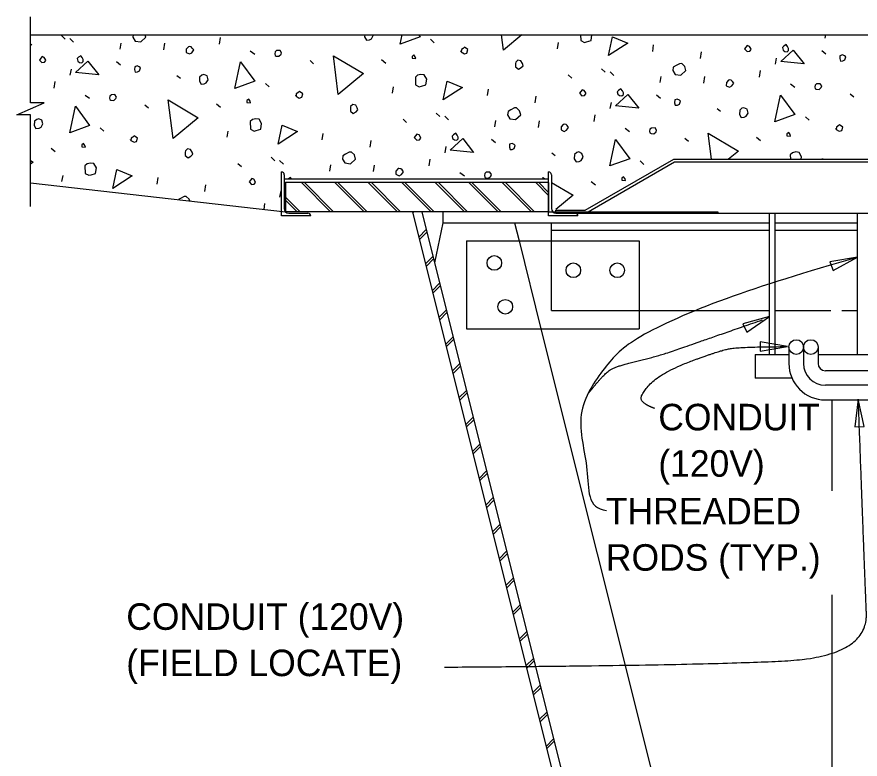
# Model space of a CAD drawing. Extents: x 927736.2 to 927809.6, y 636703.6 to 636757.7.
# Drawn here: x 927752.87 to 927764.73, y 636721.33 to 636731.77 of the extents above; entities that cross this region are included whole.
import ezdxf

# ---------------------------------------------------------------- set-up
doc = ezdxf.new("R2010")
doc.units = 0
for name, color, linetype in [('Default', 7, 'Continuous'), ('DimLines_dp', 7, 'Continuous'), ('Miscellaneous1', 7, 'Continuous'), ('Miscellaneous2', 7, 'Continuous'), ('Miscellaneous3', 7, 'Continuous')]:
    doc.layers.add(name, color=color, linetype=linetype)

msp = doc.modelspace()

# ---------------------------------------------------------------- linework, layer by layer
at = {"layer": 'Default'}
msp.add_line((927758.438, 636729.014), (927758.453, 636729.029), dxfattribs=at)
at = {"layer": 'DimLines_dp'}
msp.add_lwpolyline([(927753.063, 636729.104), (927753.063, 636730.392), (927752.871, 636730.392), (927753.063, 636730.476), (927753.254, 636730.559), (927753.063, 636730.559), (927753.063, 636731.768)], dxfattribs=at)
for points in [[(927764.692, 636728.389), (927764.306, 636728.326), (927764.349, 636728.202)], [(927763.458, 636727.557), (927763.081, 636727.455), (927763.135, 636727.336)], [(927763.711, 636727.133), (927763.325, 636727.199), (927763.325, 636727.068)], [(927764.705, 636726.393), (927764.654, 636726.006), (927764.785, 636726.011)]]:
    msp.add_lwpolyline(points, close=True, dxfattribs=at)
for points, degree in [([(927764.692, 636728.389), (927763.962, 636728.176), (927762.754, 636727.81), (927761.495, 636727.244), (927761.155, 636726.878), (927760.689, 636726.198), (927760.946, 636725.403), (927760.886, 636724.856), (927761.163, 636724.831)], 3), ([(927760.903, 636726.468), (927761.067, 636726.677), (927761.256, 636726.853), (927761.873, 636726.992), (927762.515, 636727.218), (927763.355, 636727.509)], 2), ([(927761.841, 636726.264), (927761.696, 636726.315), (927761.621, 636726.441), (927761.929, 636726.768), (927762.729, 636727.07), (927763.037, 636727.133), (927763.711, 636727.133)], 2), ([(927758.883, 636722.628), (927762.516, 636722.653), (927764.844, 636722.779), (927764.793, 636724), (927764.705, 636726.393)], 2)]:
    msp.add_open_spline(points, degree=degree, dxfattribs=at)
at = {"layer": 'Miscellaneous1'}
for p, q in [((927763.728, 636727.127), (927763.728, 636726.898)), ((927763.934, 636727.127), (927763.934, 636726.898)), ((927764.139, 636727.127), (927764.139, 636726.898)), ((927763.253, 636727.024), (927763.253, 636726.69)), ((927763.253, 636727.024), (927763.728, 636727.024)), ((927764.139, 636727.024), (927764.974, 636727.024)), ((927765.656, 636726.795), (927764.242, 636726.795)), ((927763.772, 636726.69), (927763.253, 636726.69)), ((927765.66, 636726.589), (927764.242, 636726.59)), ((927764.242, 636726.384), (927765.662, 636726.383))]:
    msp.add_line(p, q, dxfattribs=at)
for centre in [(927763.831, 636727.127), (927764.037, 636727.127)]:
    msp.add_circle(centre, 0.103, dxfattribs=at)
for radius in [0.514, 0.308, 0.103]:
    msp.add_arc((927764.242, 636726.898), radius, 180, 269.9792, dxfattribs=at)
at = {"layer": 'Miscellaneous2'}
for p, q in [((927753.063, 636731.515), (927774, 636731.515)), ((927753.498, 636731.507), (927753.55, 636731.457)), ((927753.618, 636731.463), (927753.67, 636731.413)), ((927755.72, 636731.387), (927755.733, 636731.48)), ((927758.689, 636731.455), (927758.741, 636731.405)), ((927764.24, 636731.468), (927764.248, 636731.515)), ((927753.063, 636731.391), (927753.08, 636731.376)), ((927754.322, 636731.313), (927754.337, 636731.4)), ((927754.937, 636731.305), (927754.951, 636731.398)), ((927760.475, 636731.321), (927760.49, 636731.408)), ((927761.813, 636731.283), (927761.826, 636731.376)), ((927756.154, 636731.293), (927756.217, 636731.246)), ((927762.485, 636731.183), (927762.498, 636731.275)), ((927763.54, 636731.102), (927763.555, 636731.189)), ((927764.191, 636731.295), (927764.249, 636731.247)), ((927754.273, 636731.14), (927754.331, 636731.092)), ((927756.995, 636731.155), (927757.045, 636731.11)), ((927758, 636731.168), (927758.058, 636731.12)), ((927753.623, 636730.947), (927753.638, 636731.034)), ((927755.123, 636730.946), (927755.171, 636730.908)), ((927760.625, 636730.952), (927760.675, 636730.908)), ((927761.093, 636731.039), (927761.144, 636730.989)), ((927761.213, 636730.995), (927761.265, 636730.945)), ((927763.315, 636730.92), (927763.328, 636731.013)), ((927753.397, 636730.765), (927753.41, 636730.858)), ((927756.366, 636730.833), (927756.418, 636730.783)), ((927761.917, 636730.845), (927761.932, 636730.932)), ((927762.532, 636730.838), (927762.546, 636730.931)), ((927763.749, 636730.825), (927763.812, 636730.779)), ((927758.152, 636730.698), (927758.167, 636730.785)), ((927759.49, 636730.661), (927759.503, 636730.754)), ((927753.831, 636730.67), (927753.894, 636730.624)), ((927760.161, 636730.56), (927760.175, 636730.653)), ((927761.868, 636730.673), (927761.925, 636730.624)), ((927764.59, 636730.687), (927764.64, 636730.643)), ((927754.672, 636730.532), (927754.722, 636730.488)), ((927755.677, 636730.546), (927755.735, 636730.498)), ((927761.217, 636730.479), (927761.232, 636730.566)), ((927762.718, 636730.479), (927762.766, 636730.441)), ((927758.77, 636730.417), (927758.821, 636730.367)), ((927758.89, 636730.373), (927758.942, 636730.323)), ((927760.992, 636730.297), (927761.005, 636730.39)), ((927763.961, 636730.365), (927764.013, 636730.315)), ((927758.302, 636730.33), (927758.352, 636730.286)), ((927759.594, 636730.223), (927759.609, 636730.31)), ((927760.209, 636730.215), (927760.223, 636730.308)), ((927754.043, 636730.21), (927754.095, 636730.16)), ((927755.829, 636730.076), (927755.844, 636730.163)), ((927757.167, 636730.038), (927757.18, 636730.131)), ((927761.425, 636730.203), (927761.489, 636730.156)), ((927757.838, 636729.938), (927757.852, 636730.031)), ((927759.545, 636730.05), (927759.602, 636730.002)), ((927762.267, 636730.064), (927762.317, 636730.02)), ((927763.272, 636730.078), (927763.33, 636730.03)), ((927753.354, 636729.923), (927753.412, 636729.875)), ((927758.894, 636729.857), (927758.909, 636729.944)), ((927756.447, 636729.795), (927756.498, 636729.745)), ((927758.669, 636729.675), (927758.682, 636729.768)), ((927760.395, 636729.856), (927760.443, 636729.818)), ((927760.864, 636729.049), (927762.11, 636729.768)), ((927762.11, 636729.768), (927774, 636729.768)), ((927755.978, 636729.707), (927756.029, 636729.663)), ((927756.567, 636729.75), (927756.619, 636729.7)), ((927757.271, 636729.6), (927757.286, 636729.687)), ((927757.886, 636729.593), (927757.899, 636729.686)), ((927760.874, 636729.01), (927762.121, 636729.73)), ((927761.638, 636729.743), (927761.69, 636729.693)), ((927762.121, 636729.73), (927774, 636729.73)), ((927753.506, 636729.453), (927753.521, 636729.54)), ((927756.593, 636728.972), (927756.593, 636729.588)), ((927756.631, 636729.55), (927756.631, 636729.074)), ((927759.102, 636729.58), (927759.166, 636729.534)), ((927760.35, 636728.972), (927760.35, 636729.588)), ((927760.389, 636729.55), (927760.389, 636729.074)), ((927753.063, 636729.436), (927756.65, 636729.029)), ((927754.844, 636729.416), (927754.857, 636729.509)), ((927755.515, 636729.315), (927755.529, 636729.408)), ((927756.631, 636729.491), (927760.35, 636729.491)), ((927756.631, 636729.44), (927756.65, 636729.44)), ((927757.283, 636729.029), (927756.872, 636729.44)), ((927757.326, 636729.029), (927756.915, 636729.44)), ((927757.754, 636729.029), (927757.343, 636729.44)), ((927757.797, 636729.029), (927757.386, 636729.44)), ((927758.225, 636729.029), (927757.813, 636729.44)), ((927758.268, 636729.029), (927757.857, 636729.44)), ((927758.696, 636729.029), (927758.284, 636729.44)), ((927758.739, 636729.029), (927758.328, 636729.44)), ((927759.167, 636729.029), (927758.755, 636729.44)), ((927759.21, 636729.029), (927758.799, 636729.44)), ((927759.638, 636729.029), (927759.226, 636729.44)), ((927759.681, 636729.029), (927759.27, 636729.44)), ((927760.108, 636729.029), (927759.697, 636729.44)), ((927760.152, 636729.029), (927759.741, 636729.44)), ((927760.35, 636729.258), (927760.168, 636729.44)), ((927760.35, 636729.302), (927760.212, 636729.44)), ((927760.35, 636729.44), (927760.35, 636729.029)), ((927760.949, 636729.456), (927761.007, 636729.408)), ((927756.571, 636729.234), (927756.586, 636729.321)), ((927756.856, 636729.029), (927756.65, 636729.234)), ((927756.812, 636729.029), (927756.65, 636729.191)), ((927756.347, 636729.063), (927756.359, 636729.145)), ((927760.453, 636729.049), (927760.864, 636729.049)), ((927760.453, 636729.01), (927760.453, 636729.049)), ((927757.004, 636728.971), (927756.593, 636728.972)), ((927756.695, 636729.01), (927756.965, 636729.01)), ((927760.344, 636729.029), (927760.35, 636729.035)), ((927760.344, 636729.029), (927760.35, 636729.035)), ((927760.761, 636728.972), (927760.35, 636728.972)), ((927760.453, 636729.01), (927760.723, 636729.01)), ((927760.453, 636729.01), (927774, 636729.01))]:
    msp.add_line(p, q, dxfattribs=at)
for points in [[(927754.501, 636731.482), (927754.534, 636731.427), (927754.614, 636731.417), (927754.686, 636731.481), (927754.677, 636731.515)], [(927754.505, 636731.515), (927754.501, 636731.482)], [(927757.763, 636731.515), (927757.761, 636731.488), (927757.786, 636731.443), (927757.829, 636731.448), (927757.858, 636731.462), (927757.884, 636731.508), (927757.882, 636731.515)], [(927758.261, 636731.385), (927758.289, 636731.515)], [(927758.519, 636731.515), (927758.541, 636731.486), (927758.261, 636731.385)], [(927759.714, 636731.302), (927759.687, 636731.515)], [(927759.972, 636731.515), (927759.714, 636731.302)], [(927760.799, 636731.515), (927760.802, 636731.434), (927760.853, 636731.409), (927760.883, 636731.417), (927760.949, 636731.435), (927760.959, 636731.514), (927760.959, 636731.515)], [(927761.19, 636731.225), (927761.247, 636731.489), (927761.462, 636731.4), (927761.19, 636731.225)], [(927755.254, 636731.314), (927755.254, 636731.269), (927755.297, 636731.249), (927755.331, 636731.264), (927755.359, 636731.303), (927755.339, 636731.33), (927755.323, 636731.345), (927755.296, 636731.35), (927755.284, 636731.347), (927755.254, 636731.314)], [(927756.503, 636731.227), (927756.518, 636731.218), (927756.557, 636731.216), (927756.588, 636731.243), (927756.595, 636731.264), (927756.574, 636731.297), (927756.523, 636731.296), (927756.503, 636731.278), (927756.497, 636731.251), (927756.503, 636731.227)], [(927759.12, 636731.277), (927759.166, 636731.251), (927759.201, 636731.26), (927759.214, 636731.309), (927759.167, 636731.341), (927759.146, 636731.322), (927759.124, 636731.31), (927759.12, 636731.277), (927759.117, 636731.289)], [(927763.106, 636731.317), (927763.141, 636731.282), (927763.178, 636731.285), (927763.197, 636731.31), (927763.194, 636731.322), (927763.173, 636731.354), (927763.144, 636731.366), (927763.125, 636731.341), (927763.106, 636731.317)], [(927763.613, 636731.14), (927763.787, 636731.302), (927763.941, 636731.107), (927763.613, 636731.14)], [(927763.646, 636731.302), (927763.671, 636731.283), (927763.703, 636731.279), (927763.724, 636731.298), (927763.724, 636731.323), (927763.71, 636731.351), (927763.69, 636731.378), (927763.657, 636731.356), (927763.637, 636731.338), (927763.646, 636731.302)], [(927753.188, 636731.162), (927753.223, 636731.127), (927753.26, 636731.131), (927753.28, 636731.155), (927753.276, 636731.167), (927753.255, 636731.199), (927753.226, 636731.211), (927753.207, 636731.187), (927753.188, 636731.162)], [(927753.728, 636731.147), (927753.753, 636731.128), (927753.786, 636731.124), (927753.806, 636731.143), (927753.806, 636731.168), (927753.792, 636731.196), (927753.772, 636731.223), (927753.739, 636731.201), (927753.719, 636731.183), (927753.728, 636731.147)], [(927757.391, 636730.679), (927757.322, 636731.223), (927757.746, 636730.973), (927757.391, 636730.679)], [(927758.429, 636731.188), (927758.482, 636731.183), (927758.475, 636731.206), (927758.455, 636731.233), (927758.429, 636731.213), (927758.429, 636731.188)], [(927764.444, 636731.184), (927764.454, 636731.148), (927764.485, 636731.15), (927764.513, 636731.164), (927764.527, 636731.206), (927764.511, 636731.221), (927764.482, 636731.233), (927764.446, 636731.223), (927764.444, 636731.184)], [(927753.695, 636730.985), (927753.869, 636731.147), (927754.023, 636730.952), (927753.695, 636730.985)], [(927754.526, 636731.029), (927754.536, 636730.993), (927754.567, 636730.995), (927754.595, 636731.009), (927754.61, 636731.052), (927754.593, 636731.066), (927754.564, 636731.078), (927754.529, 636731.068), (927754.526, 636731.029)], [(927755.938, 636730.763), (927756.017, 636731.135), (927756.218, 636730.863), (927755.938, 636730.763)], [(927759.886, 636731.112), (927759.885, 636731.067), (927759.926, 636731.033), (927759.965, 636731.056), (927759.99, 636731.082), (927759.982, 636731.112), (927759.959, 636731.151), (927759.918, 636731.159), (927759.887, 636731.131), (927759.886, 636731.112)], [(927762.095, 636731.014), (927762.129, 636730.96), (927762.209, 636730.949), (927762.281, 636731.013), (927762.265, 636731.073), (927762.222, 636731.112), (927762.191, 636731.11), (927762.141, 636731.084), (927762.102, 636731.061), (927762.095, 636731.014)], [(927755.442, 636730.923), (927755.438, 636730.865), (927755.463, 636730.821), (927755.506, 636730.826), (927755.535, 636730.84), (927755.561, 636730.885), (927755.546, 636730.939), (927755.503, 636730.959), (927755.473, 636730.951), (927755.442, 636730.923)], [(927758.476, 636730.919), (927758.479, 636730.811), (927758.53, 636730.787), (927758.56, 636730.795), (927758.625, 636730.812), (927758.636, 636730.892), (927758.601, 636730.953), (927758.554, 636730.959), (927758.507, 636730.947), (927758.476, 636730.919)], [(927758.867, 636730.603), (927758.924, 636730.867), (927759.139, 636730.778), (927758.867, 636730.603)], [(927762.849, 636730.846), (927762.848, 636730.801), (927762.892, 636730.781), (927762.926, 636730.797), (927762.954, 636730.836), (927762.934, 636730.862), (927762.917, 636730.877), (927762.89, 636730.883), (927762.879, 636730.88), (927762.849, 636730.846)], [(927764.098, 636730.759), (927764.113, 636730.751), (927764.152, 636730.748), (927764.183, 636730.776), (927764.19, 636730.797), (927764.169, 636730.829), (927764.118, 636730.829), (927764.097, 636730.81), (927764.092, 636730.783), (927764.098, 636730.759)], [(927756.797, 636730.655), (927756.843, 636730.628), (927756.878, 636730.638), (927756.891, 636730.686), (927756.844, 636730.718), (927756.823, 636730.7), (927756.801, 636730.688), (927756.797, 636730.655), (927756.794, 636730.666)], [(927760.783, 636730.695), (927760.818, 636730.659), (927760.855, 636730.663), (927760.874, 636730.687), (927760.871, 636730.699), (927760.85, 636730.732), (927760.821, 636730.743), (927760.802, 636730.719), (927760.783, 636730.695)], [(927761.323, 636730.68), (927761.347, 636730.661), (927761.38, 636730.657), (927761.401, 636730.675), (927761.401, 636730.701), (927761.387, 636730.729), (927761.367, 636730.755), (927761.334, 636730.734), (927761.314, 636730.716), (927761.323, 636730.68)], [(927754.18, 636730.605), (927754.195, 636730.596), (927754.234, 636730.593), (927754.265, 636730.621), (927754.272, 636730.642), (927754.251, 636730.675), (927754.2, 636730.674), (927754.179, 636730.655), (927754.174, 636730.628), (927754.18, 636730.605)], [(927755.068, 636730.057), (927754.999, 636730.6), (927755.423, 636730.35), (927755.068, 636730.057)], [(927756.106, 636730.565), (927756.159, 636730.56), (927756.152, 636730.584), (927756.132, 636730.61), (927756.106, 636730.591), (927756.106, 636730.565)], [(927761.29, 636730.518), (927761.464, 636730.679), (927761.618, 636730.484), (927761.29, 636730.518)], [(927762.121, 636730.562), (927762.131, 636730.526), (927762.162, 636730.528), (927762.19, 636730.542), (927762.204, 636730.584), (927762.188, 636730.599), (927762.159, 636730.61), (927762.123, 636730.601), (927762.121, 636730.562)], [(927763.533, 636730.295), (927763.612, 636730.667), (927763.813, 636730.396), (927763.533, 636730.295)], [(927753.615, 636730.14), (927753.694, 636730.513), (927753.895, 636730.241), (927753.615, 636730.14)], [(927757.563, 636730.489), (927757.562, 636730.445), (927757.603, 636730.411), (927757.642, 636730.434), (927757.667, 636730.46), (927757.659, 636730.49), (927757.636, 636730.528), (927757.595, 636730.536), (927757.564, 636730.509), (927757.563, 636730.489)], [(927759.772, 636730.392), (927759.806, 636730.337), (927759.886, 636730.327), (927759.958, 636730.391), (927759.942, 636730.45), (927759.899, 636730.49), (927759.868, 636730.488), (927759.818, 636730.462), (927759.779, 636730.438), (927759.772, 636730.392)], [(927763.037, 636730.456), (927763.033, 636730.397), (927763.058, 636730.353), (927763.101, 636730.358), (927763.129, 636730.372), (927763.156, 636730.417), (927763.141, 636730.471), (927763.097, 636730.491), (927763.068, 636730.483), (927763.037, 636730.456)], [(927753.119, 636730.301), (927753.115, 636730.243), (927753.14, 636730.198), (927753.183, 636730.203), (927753.212, 636730.217), (927753.238, 636730.263), (927753.223, 636730.316), (927753.18, 636730.336), (927753.15, 636730.328), (927753.119, 636730.301)], [(927756.153, 636730.297), (927756.156, 636730.189), (927756.207, 636730.164), (927756.237, 636730.172), (927756.302, 636730.19), (927756.313, 636730.269), (927756.278, 636730.33), (927756.231, 636730.337), (927756.183, 636730.324), (927756.153, 636730.297)], [(927756.544, 636729.98), (927756.601, 636730.244), (927756.816, 636730.155), (927756.544, 636729.98)], [(927760.526, 636730.224), (927760.525, 636730.179), (927760.569, 636730.159), (927760.603, 636730.174), (927760.631, 636730.213), (927760.611, 636730.24), (927760.594, 636730.255), (927760.567, 636730.26), (927760.555, 636730.257), (927760.526, 636730.224)], [(927764.392, 636730.187), (927764.437, 636730.161), (927764.473, 636730.17), (927764.486, 636730.218), (927764.439, 636730.251), (927764.418, 636730.232), (927764.396, 636730.22), (927764.392, 636730.187), (927764.389, 636730.199)], [(927758.46, 636730.072), (927758.495, 636730.037), (927758.532, 636730.041), (927758.551, 636730.065), (927758.548, 636730.077), (927758.527, 636730.109), (927758.498, 636730.121), (927758.479, 636730.096), (927758.46, 636730.072)], [(927759, 636730.057), (927759.024, 636730.038), (927759.057, 636730.034), (927759.078, 636730.053), (927759.078, 636730.078), (927759.064, 636730.106), (927759.044, 636730.133), (927759.011, 636730.111), (927758.991, 636730.093), (927759, 636730.057)], [(927761.775, 636730.137), (927761.79, 636730.128), (927761.829, 636730.126), (927761.86, 636730.153), (927761.867, 636730.174), (927761.846, 636730.207), (927761.795, 636730.206), (927761.774, 636730.188), (927761.769, 636730.161), (927761.775, 636730.137)], [(927762.64, 636729.768), (927762.593, 636730.133), (927763.018, 636729.883), (927762.879, 636729.768)], [(927763.701, 636730.098), (927763.753, 636730.092), (927763.747, 636730.116), (927763.727, 636730.143), (927763.701, 636730.123), (927763.701, 636730.098)], [(927754.474, 636730.032), (927754.519, 636730.006), (927754.555, 636730.016), (927754.568, 636730.064), (927754.521, 636730.096), (927754.5, 636730.077), (927754.478, 636730.065), (927754.474, 636730.032), (927754.471, 636730.044)], [(927758.967, 636729.895), (927759.141, 636730.057), (927759.295, 636729.862), (927758.967, 636729.895)], [(927761.21, 636729.673), (927761.289, 636730.045), (927761.49, 636729.773), (927761.21, 636729.673)], [(927753.783, 636729.943), (927753.836, 636729.938), (927753.829, 636729.961), (927753.809, 636729.988), (927753.783, 636729.968), (927753.783, 636729.943)], [(927755.24, 636729.867), (927755.239, 636729.822), (927755.28, 636729.788), (927755.319, 636729.811), (927755.344, 636729.837), (927755.336, 636729.867), (927755.312, 636729.906), (927755.272, 636729.914), (927755.241, 636729.886), (927755.24, 636729.867)], [(927759.798, 636729.939), (927759.808, 636729.903), (927759.839, 636729.905), (927759.867, 636729.919), (927759.881, 636729.962), (927759.865, 636729.976), (927759.836, 636729.988), (927759.8, 636729.978), (927759.798, 636729.939)], [(927757.449, 636729.77), (927757.483, 636729.715), (927757.563, 636729.704), (927757.635, 636729.768), (927757.619, 636729.828), (927757.576, 636729.867), (927757.545, 636729.865), (927757.495, 636729.839), (927757.456, 636729.816), (927757.449, 636729.77)], [(927760.714, 636729.833), (927760.71, 636729.775), (927760.735, 636729.731), (927760.778, 636729.736), (927760.806, 636729.75), (927760.833, 636729.795), (927760.818, 636729.849), (927760.774, 636729.869), (927760.745, 636729.861), (927760.714, 636729.833)], [(927763.903, 636729.768), (927763.908, 636729.802), (927763.872, 636729.863), (927763.826, 636729.869), (927763.778, 636729.857), (927763.747, 636729.829)], [(927763.747, 636729.829), (927763.749, 636729.768)], [(927764.194, 636729.768), (927764.195, 636729.777), (927764.216, 636729.768)], [(927753.063, 636729.75), (927753.1, 636729.728), (927753.063, 636729.697)], [(927753.829, 636729.674), (927753.833, 636729.567), (927753.884, 636729.542), (927753.914, 636729.55), (927753.979, 636729.568), (927753.99, 636729.647), (927753.955, 636729.708), (927753.908, 636729.714), (927753.86, 636729.702), (927753.829, 636729.674)], [(927758.203, 636729.601), (927758.202, 636729.556), (927758.246, 636729.536), (927758.28, 636729.552), (927758.308, 636729.591), (927758.288, 636729.618), (927758.271, 636729.632), (927758.244, 636729.638), (927758.232, 636729.635), (927758.203, 636729.601)], [(927754.221, 636729.358), (927754.278, 636729.622), (927754.493, 636729.533), (927754.221, 636729.358)], [(927759.452, 636729.515), (927759.467, 636729.506), (927759.506, 636729.503), (927759.537, 636729.531), (927759.544, 636729.552), (927759.523, 636729.584), (927759.472, 636729.584), (927759.451, 636729.565), (927759.446, 636729.538), (927759.452, 636729.515)], [(927761.378, 636729.475), (927761.43, 636729.47), (927761.424, 636729.494), (927761.404, 636729.52), (927761.377, 636729.501), (927761.378, 636729.475)], [(927756.137, 636729.45), (927756.172, 636729.414), (927756.209, 636729.418), (927756.228, 636729.442), (927756.225, 636729.454), (927756.204, 636729.487), (927756.175, 636729.498), (927756.156, 636729.474), (927756.137, 636729.45)], [(927756.735, 636729.491), (927756.721, 636729.51), (927756.692, 636729.491)], [(927760.273, 636729.491), (927760.27, 636729.51), (927760.303, 636729.491)], [(927760.389, 636729.441), (927760.695, 636729.26), (927760.451, 636729.059)], [(927755.302, 636729.182), (927755.296, 636729.205), (927755.253, 636729.245), (927755.222, 636729.243), (927755.171, 636729.217), (927755.144, 636729.2)]]:
    msp.add_lwpolyline(points, dxfattribs=at)
for centre, radius, start, end in [((927756.593, 636729.55), 0.0385, 359.9953, 89.9953), ((927760.35, 636729.55), 0.0385, 359.9953, 89.9953), ((927756.695, 636729.074), 0.0642, 179.9953, 269.9953), ((927760.453, 636729.074), 0.0642, 179.9953, 269.9953), ((927756.965, 636728.971), 0.0385, 359.9953, 89.9953), ((927760.723, 636728.972), 0.0385, 359.9953, 89.9953)]:
    msp.add_arc(centre, radius, start, end, dxfattribs=at)
at = {"layer": 'Miscellaneous3'}
for p, q in [((927760.35, 636729.44), (927756.65, 636729.44)), ((927756.65, 636729.44), (927756.65, 636729.029)), ((927760.35, 636729.029), (927756.65, 636729.029)), ((927758.434, 636729.029), (927762.288, 636713.612)), ((927758.566, 636729.029), (927762.42, 636713.612)), ((927758.867, 636728.875), (927758.867, 636729.029)), ((927760.35, 636729.029), (927762.729, 636729.029)), ((927762.729, 636729.029), (927762.729, 636729.01)), ((927763.458, 636727.024), (927763.458, 636729.01)), ((927763.535, 636727.024), (927763.535, 636729.01)), ((927764.692, 636727.024), (927764.692, 636729.01)), ((927758.862, 636728.875), (927758.745, 636728.313)), ((927758.867, 636728.875), (927763.458, 636728.875)), ((927759.868, 636728.875), (927759.933, 636728.618)), ((927760.389, 636728.592), (927760.389, 636728.875)), ((927763.535, 636728.875), (927764.692, 636728.874)), ((927758.523, 636728.672), (927758.629, 636728.778)), ((927758.532, 636728.637), (927758.638, 636728.743)), ((927760.389, 636727.641), (927760.389, 636728.772)), ((927760.389, 636728.772), (927763.458, 636728.772)), ((927763.535, 636728.772), (927764.692, 636728.772)), ((927759.194, 636728.618), (927759.194, 636727.384)), ((927759.194, 636728.618), (927761.622, 636728.618)), ((927759.933, 636728.618), (927760.241, 636727.384)), ((927761.622, 636728.618), (927761.622, 636727.384)), ((927758.617, 636728.295), (927758.723, 636728.401)), ((927758.626, 636728.26), (927758.732, 636728.366)), ((927758.711, 636727.918), (927758.817, 636728.024)), ((927758.72, 636727.883), (927758.826, 636727.989)), ((927758.806, 636727.542), (927758.912, 636727.648)), ((927760.389, 636727.641), (927761.622, 636727.641)), ((927761.622, 636727.641), (927763.458, 636727.641)), ((927763.535, 636727.641), (927764.319, 636727.641)), ((927764.473, 636727.641), (927764.692, 636727.641)), ((927758.814, 636727.507), (927758.92, 636727.613)), ((927759.194, 636727.384), (927761.622, 636727.384)), ((927760.241, 636727.384), (927762.676, 636717.646)), ((927758.9, 636727.165), (927759.006, 636727.271)), ((927758.909, 636727.13), (927759.015, 636727.236)), ((927758.994, 636726.788), (927759.1, 636726.894)), ((927759.003, 636726.753), (927759.109, 636726.859)), ((927759.088, 636726.411), (927759.194, 636726.517)), ((927759.097, 636726.376), (927759.203, 636726.482)), ((927759.182, 636726.035), (927759.288, 636726.141)), ((927759.191, 636726), (927759.297, 636726.106)), ((927759.277, 636725.658), (927759.383, 636725.764)), ((927759.285, 636725.623), (927759.391, 636725.729)), ((927759.371, 636725.281), (927759.477, 636725.387)), ((927759.379, 636725.246), (927759.485, 636725.352)), ((927759.465, 636724.904), (927759.571, 636725.01)), ((927759.474, 636724.869), (927759.58, 636724.975)), ((927759.559, 636724.528), (927759.665, 636724.634)), ((927759.568, 636724.493), (927759.674, 636724.599)), ((927759.653, 636724.151), (927759.759, 636724.257)), ((927759.662, 636724.116), (927759.768, 636724.222)), ((927759.748, 636723.774), (927759.853, 636723.88)), ((927759.756, 636723.739), (927759.862, 636723.845)), ((927759.842, 636723.397), (927759.948, 636723.503)), ((927759.85, 636723.362), (927759.956, 636723.468)), ((927759.936, 636723.021), (927760.042, 636723.127)), ((927759.945, 636722.986), (927760.051, 636723.092)), ((927760.03, 636722.644), (927760.136, 636722.75)), ((927760.039, 636722.609), (927760.145, 636722.715)), ((927760.124, 636722.267), (927760.23, 636722.373)), ((927760.133, 636722.232), (927760.239, 636722.338)), ((927760.218, 636721.89), (927760.324, 636721.996)), ((927760.227, 636721.856), (927760.333, 636721.961)), ((927760.313, 636721.514), (927760.419, 636721.62)), ((927760.321, 636721.479), (927760.427, 636721.585))]:
    msp.add_line(p, q, dxfattribs=at)
for points in [[(927764.332, 636726.384), (927764.332, 636725.108)], [(927764.332, 636723.646), (927764.332, 636718.446), (927768.032, 636718.446)]]:
    msp.add_lwpolyline(points, dxfattribs=at)
for centre in [(927759.586, 636728.309), (927760.697, 636728.206), (927761.314, 636728.206), (927759.74, 636727.693)]:
    msp.add_circle(centre, 0.103, dxfattribs=at)

# ---------------------------------------------------------------- texts
at = {"layer": 'DimLines_dp'}
for s, height, p in [('CONDUIT', 0.373, (927761.892, 636725.956)), ('(120V)', 0.373, (927761.892, 636725.304)), ('THREADED', 0.373, (927761.155, 636724.634)), ('RODS (TYP.)', 0.37296, (927761.155, 636723.983)), ('CONDUIT (120V)', 0.37296, (927754.41, 636723.152)), ('(FIELD LOCATE)', 0.37296, (927754.41, 636722.501))]:
    msp.add_text(s, height=height, dxfattribs=at).set_placement(p)

doc.saveas('drawing.dxf')
